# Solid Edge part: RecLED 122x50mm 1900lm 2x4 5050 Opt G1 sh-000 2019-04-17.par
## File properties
Author: sylwester.cabaj
Template: iso metric part.par
Last saved by: sylwester.cabaj
Revision: 2
Application: Solid Edge
Gęstość: 0,000 kg/m^3
Dokładność: 0,990
Username: sylwester.cabaj
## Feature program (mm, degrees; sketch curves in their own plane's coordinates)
body "unnamed Body 1"
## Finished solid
Body 1: solid body, 448 faces, 1115 edges, 675 vertices.
  Faces by surface: plane 208, cylinder 112, spline 80, cone 20, torus 11, sphere 10, spun 7
  Edges by curve: line 602, curve on surface 278, circle 137, ellipse 60, spline 32, intersection 6
Bounding box of the edges (mm; curved faces can reach further): 49.500 x 4.900 x 121.400, from (-24.75, -3.4, -60.7) to (24.75, 1.5, 60.7).
Cylindrical faces by radius (mm): R0.2 x39, R0.2002 x2, R0.2169 x3, R0.25 x8, R0.3 x2, R0.3373 x3, R0.4 x8, R0.4006 x2, R0.4008 x2, R0.525 x2, R0.6 x8, R1 x7, R1.05 x8, R1.0894 x2, R1.1 x14, R1.6 x2
Conical faces (half-angle, radius in mm at the cone's reference point): 0.5 deg R0.5056 x4, 0.5 deg R1.0082 x4, 1 deg R0.5511 x2, 10 deg R0.2132 x2, 10 deg R0.4132 x2, 18.4844 deg R1.0657 x4, 27.363 deg R0.6214 x2
Toroidal faces (ring radius, tube radius in mm): R0.1 r0.2 x1, R0.8 r0.2 x4, R0.8522 r0.3 x2, R0.9002 r0.2 x1, R0.9018 r0.2 x1, R1.3 r0.2 x2
Spherical faces by radius (mm): R0.2 x8, R0.6 x2
Planar faces by outward normal: +x 19, +y 7, +z 17, -x 19, -y 36, -z 26, oblique 84
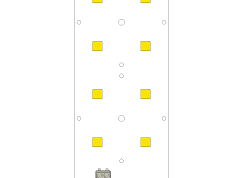
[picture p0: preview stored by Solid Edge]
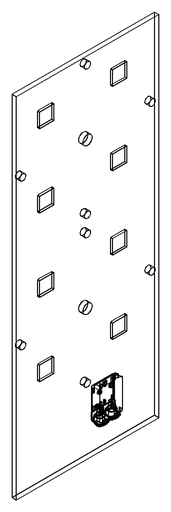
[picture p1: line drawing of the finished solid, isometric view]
